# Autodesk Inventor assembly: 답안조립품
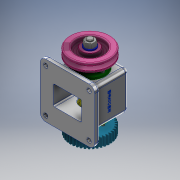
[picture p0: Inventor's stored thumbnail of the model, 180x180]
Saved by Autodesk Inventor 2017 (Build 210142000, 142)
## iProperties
Part Number: 답안조립품
Material: 일반
Document SubType Name: Assembly
Designer: MRC
Author: MRC
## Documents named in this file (12)
- C:\Users\MRC\Desktop\720706V1019\답안조립품.iam
- C:\Users\MRC\Desktop\720706V1019\V벨트풀리.ipt
- C:\Users\MRC\Desktop\720706V1019\너트 M12x1.25.ipt
- C:\Users\MRC\Desktop\720706V1019\베어링 6204.ipt
- C:\Users\MRC\Desktop\720706V1019\본체.ipt
- C:\Users\MRC\Desktop\720706V1019\볼트 M4x0.7.ipt
- C:\Users\MRC\Desktop\720706V1019\스퍼기어.ipt
- C:\Users\MRC\Desktop\720706V1019\오일실 20x35x8.ipt
- C:\Users\MRC\Desktop\720706V1019\와셔 12x24.ipt
- C:\Users\MRC\Desktop\720706V1019\축.ipt
- C:\Users\MRC\Desktop\720706V1019\커버.ipt
- C:\Users\MRC\Desktop\720706V1019\키 5x5.ipt
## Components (1 placed, 1 different names)
1. V벨트풀리:1
